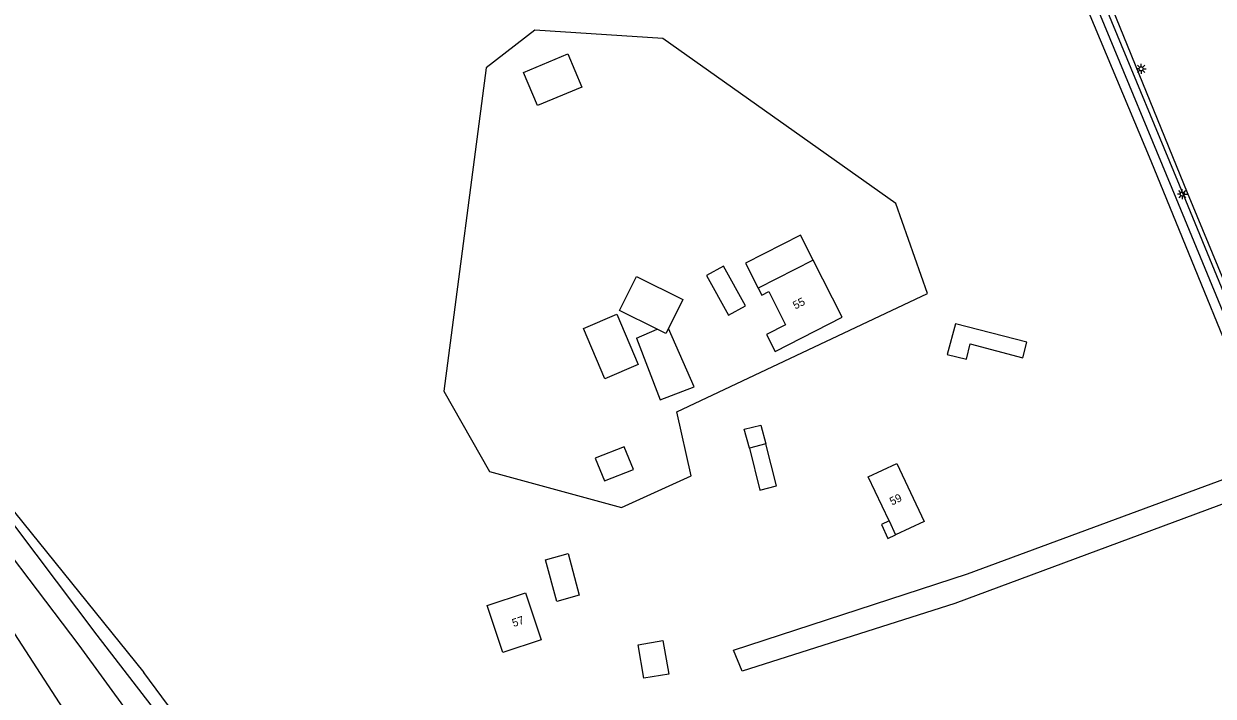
# Model space of a CAD drawing. Extents: x 124000 to 129000, y 395500 to 397503.
# Drawn here: x 128356.1 to 128504.7, y 396242.7 to 396326.7 of the extents above; entities that cross this region are included whole.
import ezdxf

# ---------------------------------------------------------------- set-up
doc = ezdxf.new("R2010")
doc.units = 0
for name, color, linetype in [('gg-afsc-draadraster', 7, 'Continuous'), ('gg-afsc-hekwerk', 7, 'Continuous'), ('gg-anno-huisnummerreeks BGT', 7, 'Continuous'), ('gg-bbg-bijgebouw', 7, 'Continuous'), ('gg-bbg-gedigitaliseerde bijgebouw', 7, 'Continuous'), ('gg-bbg-hoofdgebouw', 7, 'Continuous'), ('gg-bbg-luifel en loopbrug', 7, 'Continuous'), ('gg-knt-onverhard', 7, 'Continuous'), ('gg-knt-verharding', 7, 'Continuous'), ('gt-grn-groengrens', 7, 'Continuous'), ('gt-grn-groengrens NZ', 7, 'Continuous'), ('gt-grn-vlakafsluiter', 7, 'Continuous'), ('gt-symb-lichtmast', 7, 'Continuous')]:
    doc.layers.add(name, color=color, linetype=linetype)

# ---------------------------------------------------------------- blocks, each defined once
blk = doc.blocks.new('gt0-LMAST')
at = {"layer": 'gt-symb-lichtmast'}
for p, q in [((-0.18, 0.17), (-0.45, 0.44)), ((-0.01, 0.25), (-0.01, 0.62)), ((0.17, 0.17), (0.44, 0.44)), ((-0.26, 0), (-0.63, 0)), ((-0.18, -0.18), (-0.45, -0.45)), ((-0.01, -0.25), (-0.01, -0.63)), ((0.44, -0.45), (0.17, -0.18)), ((0.24, 0), (0.62, 0))]:
    blk.add_line(p, q, dxfattribs=at)
blk.add_circle((-0.01, 0), 0.25, dxfattribs=at)

msp = doc.modelspace()

# ---------------------------------------------------------------- linework, layer by layer
at = {"layer": 'gg-afsc-draadraster'}
msp.add_lwpolyline([(128315.62, 396314.57), (128338.72, 396285.78), (128371.11, 396245.69)], dxfattribs=at)
at = {"layer": 'gg-afsc-hekwerk'}
for points in [[(128512.25, 396272.18), (128496.93, 396309.57), (128487.83, 396331.4), (128487.33, 396331.19)], [(128382.4, 396229.98), (128374.86, 396240.57), (128371.11, 396245.69)]]:
    msp.add_lwpolyline(points, dxfattribs=at)
at = {"layer": 'gg-bbg-bijgebouw'}
msp.add_line((128448.81, 396274.25), (128446.75, 396273.73), dxfattribs=at)
for points in [[(128443.51, 396296.47), (128441.38, 396295.3), (128444.12, 396290.33), (128446.25, 396291.5), (128443.51, 396296.47)], [(128427.47, 396272.46), (128428.63, 396269.64), (128432.25, 396271.08), (128431.1, 396273.91), (128427.47, 396272.46)], [(128446.75, 396273.73), (128448.07, 396268.49), (128450.13, 396269.01), (128448.81, 396274.25)], [(128421.29, 396259.77), (128424.1, 396260.55), (128425.5, 396255.36), (128422.7, 396254.58), (128421.29, 396259.77)]]:
    msp.add_lwpolyline(points, dxfattribs=at)
at = {"layer": 'gg-bbg-gedigitaliseerde bijgebouw'}
for points in [[(128418.53, 396320.67), (128424.06, 396322.98), (128425.8, 396318.83), (128420.26, 396316.52), (128418.53, 396320.67)], [(128426.03, 396288.68), (128430.2, 396290.45), (128432.86, 396284.16), (128428.69, 396282.4), (128426.03, 396288.68)]]:
    msp.add_lwpolyline(points, dxfattribs=at)
at = {"layer": 'gg-bbg-hoofdgebouw'}
for p, q in [((128454.7, 396297.22), (128447.83, 396293.72)), ((128464.2, 396264.64), (128465.02, 396262.89))]:
    msp.add_line(p, q, dxfattribs=at)
for points in [[(128447.83, 396293.72), (128448.29, 396292.83), (128449.17, 396293.28), (128451.28, 396289.13), (128448.88, 396287.91), (128449.95, 396285.81), (128458.34, 396290.08), (128454.7, 396297.22)], [(128464.2, 396264.64), (128461.61, 396270.15), (128465.16, 396271.81), (128468.57, 396264.56), (128465.02, 396262.89)], [(128414, 396254.05), (128418.79, 396255.65), (128420.74, 396249.79), (128415.95, 396248.2), (128414, 396254.05)]]:
    msp.add_lwpolyline(points, dxfattribs=at)
at = {"layer": 'gg-bbg-luifel en loopbrug'}
msp.add_line((128432.63, 396287.47), (128435.21, 396288.61), dxfattribs=at)
for points in [[(128454.7, 396297.22), (128453.12, 396300.34), (128446.25, 396296.84), (128447.83, 396293.72)], [(128435.21, 396288.61), (128430.53, 396290.92), (128432.63, 396295.18), (128438.43, 396292.31), (128436.63, 396288.66)], [(128432.63, 396287.47), (128435.6, 396279.77), (128439.84, 396281.4), (128436.63, 396288.66)], [(128436.63, 396288.66), (128436.33, 396288.05), (128435.21, 396288.61)], [(128472.51, 396289.24), (128471.46, 396285.43), (128473.86, 396284.83), (128474.34, 396286.76), (128480.9, 396285.03), (128481.41, 396286.96), (128472.51, 396289.24)], [(128446.75, 396273.73), (128446.1, 396276.1), (128448.17, 396276.6), (128448.81, 396274.25)], [(128464.2, 396264.64), (128463.24, 396264.19), (128464.06, 396262.44), (128465.02, 396262.89)], [(128432.85, 396249.14), (128435.95, 396249.68), (128436.67, 396245.51), (128433.56, 396244.98), (128432.85, 396249.14)]]:
    msp.add_lwpolyline(points, dxfattribs=at)
at = {"layer": 'gg-knt-onverhard'}
for points in [[(128471.19, 396111.57), (128470.07, 396113), (128461.57, 396123.66), (128443.99, 396146.03), (128425.27, 396170.03), (128406.23, 396194.29), (128388.8, 396218.38), (128380.31, 396230.88), (128365.27, 396250.36), (128349.96, 396270.62), (128337.78, 396284.84), (128299.36, 396333.03)], [(128337.04, 396281.59), (128348.21, 396268.54), (128362.96, 396249.12), (128378.57, 396227.68), (128386.98, 396216.76), (128404.05, 396192.76), (128423.45, 396167.77), (128441.79, 396144.49), (128467.95, 396111.47), (128490.41, 396083.32), (128489.95, 396081)], [(128444.77, 396248.49), (128473.98, 396258.01), (128510.99, 396271.68)], [(128512.03, 396269.03), (128472.42, 396254.32), (128445.84, 396245.86), (128444.77, 396248.49)]]:
    msp.add_lwpolyline(points, dxfattribs=at)
at = {"layer": 'gg-knt-verharding'}
for points in [[(128408.31, 396528.99), (128413.98, 396515.8), (128423.9, 396492.54), (128433.42, 396469.86), (128443.11, 396446.89), (128462.95, 396399.43), (128473.06, 396374.97), (128482.54, 396351.97), (128492.12, 396328.58), (128501.46, 396305.66), (128511.03, 396282.55), (128520.46, 396259.72), (128530.31, 396236.5), (128540, 396213.49), (128549.69, 396190.63), (128593.25, 396087.47)], [(128471.96, 396375.92), (128481.9, 396351.73), (128491.48, 396328.22), (128500.95, 396305.4), (128510.43, 396282.35), (128519.89, 396259.42), (128529.8, 396236.31), (128539.45, 396213.14), (128568.59, 396144.48), (128578.2, 396121.52), (128588.03, 396098.55), (128591.59, 396089.96)]]:
    msp.add_lwpolyline(points, dxfattribs=at)
at = {"layer": 'gt-grn-groengrens'}
msp.add_lwpolyline([(128476.72, 396080.55), (128476.37, 396092.92), (128462.74, 396108.27), (128441.57, 396137.37), (128417.76, 396168.2), (128398.84, 396190.16), (128361.01, 396241.22), (128352.54, 396254.19), (128351.08, 396254.42)], dxfattribs=at)
at = {"layer": 'gt-grn-groengrens NZ'}
msp.add_lwpolyline([(128471.04, 396375.54), (128480.97, 396351.35), (128490.56, 396327.84), (128500.03, 396305.02), (128509.51, 396281.97), (128518.97, 396259.03), (128528.88, 396235.92), (128538.53, 396212.75), (128567.67, 396144.1), (128577.28, 396121.13), (128587.11, 396098.16), (128590.66, 396089.58)], dxfattribs=at)
at = {"layer": 'gt-grn-vlakafsluiter'}
msp.add_lwpolyline([(128465.06, 396304.28), (128435.94, 396324.89), (128419.96, 396325.97), (128413.86, 396321.23), (128408.58, 396280.83), (128414.27, 396270.79), (128430.79, 396266.32), (128439.46, 396270.25), (128437.7, 396278.25), (128468.99, 396293.03), (128465.06, 396304.28)], dxfattribs=at)

# ---------------------------------------------------------------- block references
at = {"layer": 'gt-symb-lichtmast'}
for p in [(128495.7, 396321.12), (128500.85, 396305.47)]:
    msp.add_blockref('gt0-LMAST', p, dxfattribs=at)

# ---------------------------------------------------------------- texts
at = {"layer": 'gg-anno-huisnummerreeks BGT'}
for s, rotation, p in [('55', 27, (128452.49, 396291.04)), ('59', 25.2, (128464.56, 396266.55)), ('57', 18.4, (128417.29, 396251.37))]:
    msp.add_text(s, height=1, rotation=rotation, dxfattribs=at).set_placement(p)

doc.saveas('drawing.dxf')
